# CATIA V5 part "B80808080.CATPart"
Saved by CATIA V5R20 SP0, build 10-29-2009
Part number: B80808080
Revision: 2
Definition: design
Nomenclature: B80808080
Source: made
Description: NOT SPECIFIED
Bounding box of the stored display mesh (mm): x -5.85 to 5.85, y -6 to 6, z 0 to 80
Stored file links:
  C:\Users\Raffaele\Desktop\3D X SITO CF\BOLEX\4-PILLAR REF 808\B80808080.CATPart
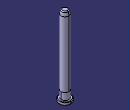
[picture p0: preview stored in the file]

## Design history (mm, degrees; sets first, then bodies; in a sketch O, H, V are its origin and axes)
Body1 "MANIFOLD_SOLID_BREP #450" (main body)
  Solid1: solid without history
